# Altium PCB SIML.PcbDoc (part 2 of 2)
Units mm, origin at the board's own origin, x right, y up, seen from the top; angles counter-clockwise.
Board outline 80.5 x 51.25 mm, 2 copper layers (Top Layer, Top, Bottom Layer, Bottom), stack 1.571 mm thick; 94 components, 58 nets, 279 pads, 160 vias.
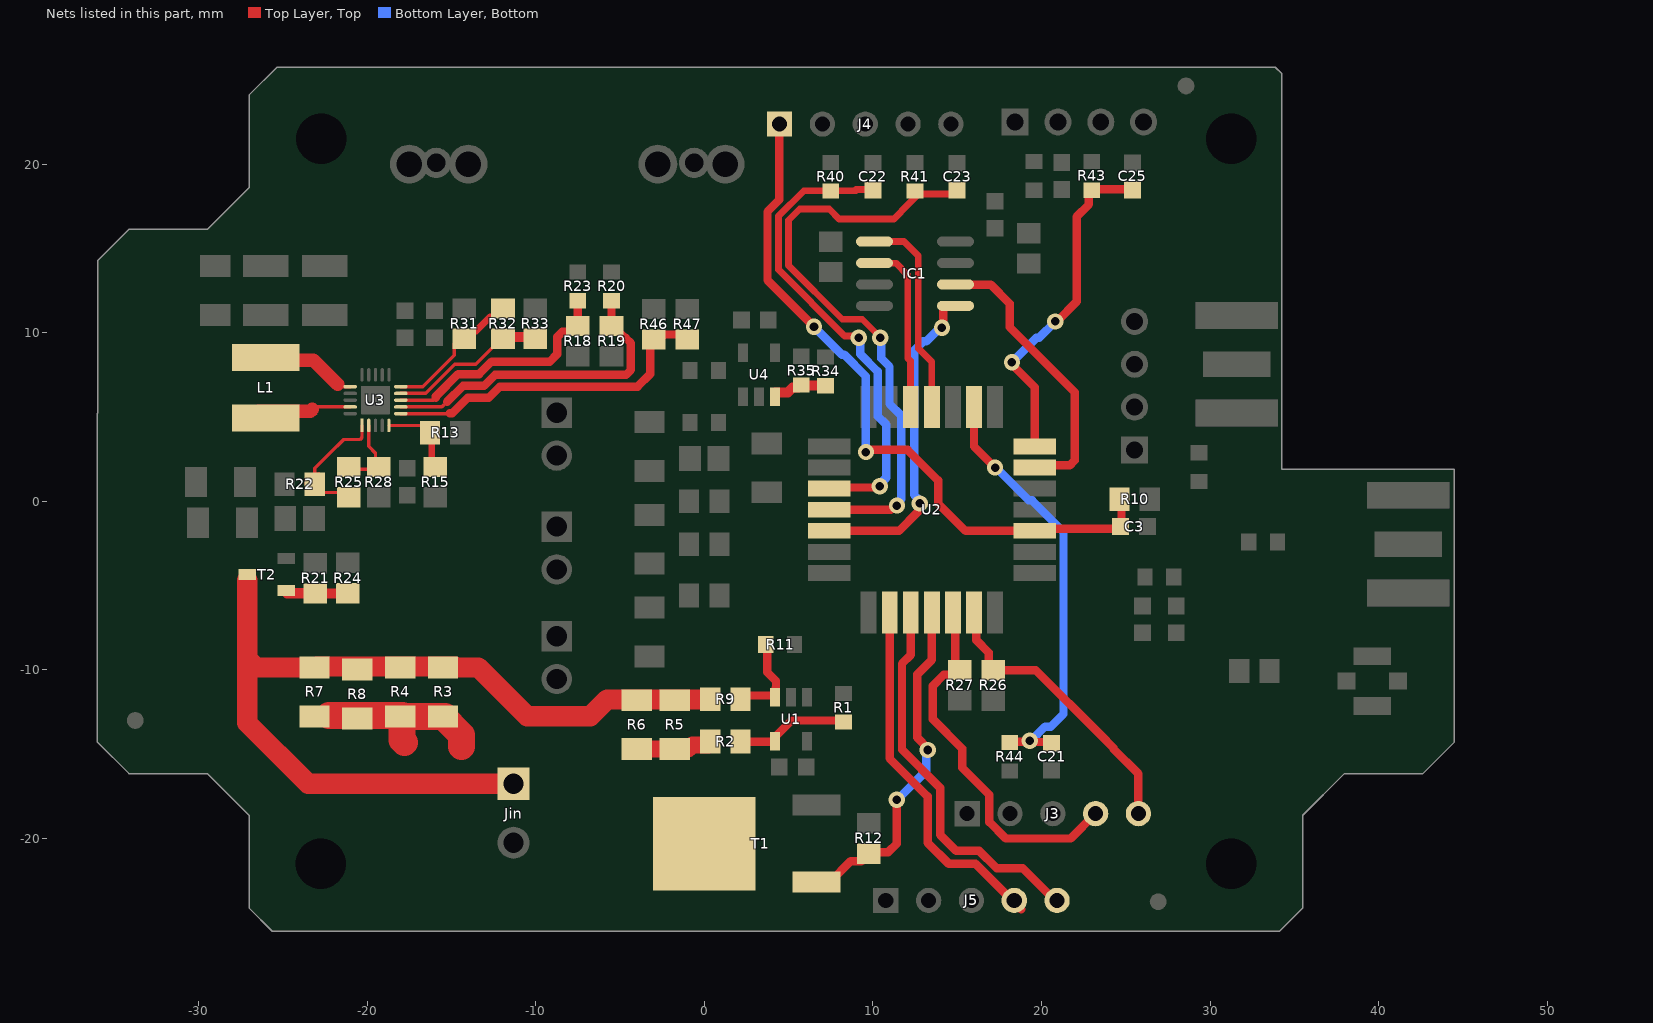
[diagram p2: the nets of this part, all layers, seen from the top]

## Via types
v1: diameter 0.965, hole 0.508, Top Layer, Top to Bottom Layer, Bottom, tented both sides, 146 vias
v2: diameter 0.8, hole 0.4, Top Layer, Top to Bottom Layer, Bottom, tented both sides, 10 vias
v3: diameter 0.965, hole 0.508, Top Layer, Top to Bottom Layer, Bottom, 4 vias

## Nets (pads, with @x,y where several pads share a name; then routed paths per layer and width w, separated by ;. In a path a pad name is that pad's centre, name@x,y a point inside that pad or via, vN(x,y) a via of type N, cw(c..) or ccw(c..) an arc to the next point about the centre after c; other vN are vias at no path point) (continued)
NetJin_1: Jin.1 R3.1 R4.1 R5.1 R6.1 R7.1 R8.1 R9.1 T2.3 | length 55.1
  Top Layer, Top w1.2: T2.3@-27.1,-4.673 -27.1,-9.349 ; R7.1@-23.114,-9.853 -26.596,-9.853 -27.1,-9.349 ; R7.1@-22.987,-9.8 -18.034,-9.8 -14.75,-9.8 -14.7,-9.85 -13.4,-9.85 -10.5,-12.75 -6.75,-12.75 -5.75,-11.75 -4,-11.75 R9.1@0.35,-11.75 ; Jin.1@-11.592,-17.033 Jin.1@-11.58,-17.045 ; Jin.1@-11.455,-16.92 Jin.1@-11.455,-16.753 ; Jin.1@-11.311,-16.753 Jin.1@-11.455,-16.753 ; -27.1,-9.349 -27.1,-13.15 -23.497,-16.753 Jin.1@-11.455,-16.753
NetL1_1: L1.1 U3.19 | length 6
  Top Layer, Top w0.2: -23.241,5.448 -23.088,5.6 U3.19@-21,5.6
  Top Layer, Top w0.8: L1.1@-26.8,5 -26.467,5.333 -23.356,5.333 -23.241,5.448
NetL1_2: L1.2 U3.16 | length 5.5
  Top Layer, Top w0.2: -21.749,6.941 -21.608,6.8 U3.16@-21,6.8
  Top Layer, Top w0.8: L1.2@-25.868,8.379 -23.187,8.379 -21.749,6.941
NetR1_1: R1.1 R2.2 U1.4 | length 6.8
  Top Layer, Top w0.5: R2.2@1.9,-14.25 U1.4@4.172,-14.25 ; U1.4@4.184,-13.987 4.251,-13.921 4.263,-13.921 5.184,-13 8.15,-13 R1.1@8.25,-13.1
NetR2_1: R2.1 R3.2 R4.2 R5.2 R6.2 R7.2 R8.2 T1.3 | length 15.4
  Top Layer, Top w1: R6.2@-4,-14.7 R5.2@-1.75,-14.7 -0.95,-14.7 -0.7,-14.45 0.25,-14.45 0.35,-14.35 R2.1@0.35,-14.25
  Top Layer, Top w1.6: R7.2@-22.25,-12.7 -20.447,-12.7 -19.75,-12.7 R4.2@-17.907,-12.7 ; R4.2@-18.034,-12.753 -17.934,-12.853 -17.934,-14.153 -17.784,-14.303 ; R4.2@-17.907,-12.753 R3.2@-15.367,-12.753 ; R3.2@-15.494,-12.753 -14.393,-13.854 -14.393,-14.549
NetR9_2: R9.2 R11.2 U1.3 | length 5.6
  Top Layer, Top w0.5: R9.2@1.908,-11.519 4.201,-11.519 4.251,-11.469 4.251,-11.075 4.256,-11.07 4.256,-10.656 3.749,-10.149 3.749,-8.599 R11.2@3.65,-8.5
NetR13_1: R13.1 R15.2 U3.5 | length 6.1
  Top Layer, Top w0.2: U3.5@-18.7,4.5 -16.703,4.5 -16.072,3.869 -16.072,2.113 R15.2@-16.002,2.043 ; R15.2@-16.256,2.143 R13.1@-16.256,3.451
NetR18_1: R18.1 R23.1 U3.8 | length 14.5
  Top Layer, Top w0.2: U3.8@-18,6 -16.065,6 -15.915,6.15
  Top Layer, Top w0.5: -15.915,6.15 -15.915,6.23 -14.598,7.548 -13.354,7.548 -12.615,8.287 -9.157,8.287 -8.717,8.727 -8.717,9.757 -8.424,10.05 -7.85,10.05 R18.1@-7.5,10.4 R23.1@-7.5,11.9
NetR19_1: R19.1 R20.1 U3.7 | length 19.2
  Top Layer, Top w0.2: U3.7@-18,5.6 -15.555,5.6 -15.241,5.914
  Top Layer, Top w0.5: -15.241,5.914 -14.308,6.848 -13.064,6.848 -12.411,7.5 -4.643,7.5 -4.35,7.793 -4.35,9.386 -4.66,9.696 -4.696,9.696 -5.4,10.4 R19.1@-5.5,10.4 R20.1@-5.5,11.9
NetR21_1: R21.1 R24.2 T2.1 | length 3.6
  Top Layer, Top w0.6: T2.1@-24.748,-5.466 -24.558,-5.466 -24.548,-5.456 R21.1@-23.106,-5.456 ; R21.1@-23.075,-5.475 -23.063,-5.462 -21.162,-5.462 R24.2@-21.15,-5.45
NetR22_1: R22.1 R25.2 U3.1 | length 9.8
  Top Layer, Top w0.2: R22.1@-23.603,1.016 -23.603,1.109 -23.103,1.609 R22.1@-22.872,1.609 ; R22.1@-23.104,1.017 -23.104,1.953 ; R22.1@-23.104,1.609 -23.104,1.953 ; R22.1@-22.853,1.628 -22.672,1.447 R22.1@-23.103,1.016 -22.611,0.524 -21.49,0.524 R25.2@-21.082,0.116 ; U3.1@-20.3,4.5 -20.3,3.784 -20.417,3.667 -21.386,3.667 -22.237,2.816 -22.241,2.816 -23.104,1.953
NetR25_1: R25.1 R28.2 U3.2 | length 4.8
  Top Layer, Top w0.2: R25.1@-21.5,1.9 -19.5,1.9 -19.5,2.863 -19.9,3.263 U3.2@-19.9,4.5
NetR31_1: R31.1 R32.2 U3.10 | length 8.1
  Top Layer, Top w0.2: U3.10@-18,6.8 -16.975,6.8 -16.689,6.8 -14.824,8.665 -14.824,9.339 R31.1@-14.5,9.663
  Top Layer, Top w0.3: R31.1@-14.224,9.641 -13.99,9.641 -13.99,9.775 -13.674,10.091 R31.1@-13.54,10.091 ; -12.681,10.95 -12.664,10.95 -12.623,10.991 -12.409,10.991 R32.2@-12,11.4
  Top Layer, Top w0.4: R31.1@-13.54,10.091 -12.681,10.95
NetR32_1: R32.1 R33.2 U3.9 | length 9.2
  Top Layer, Top w0.2: U3.9@-18,6.4 -16.523,6.4 -14.795,8.128 -13.551,8.128 -12.25,9.429 R32.1@-12.25,9.5
  Top Layer, Top w0.6: R32.1@-12.25,9.6 -12.1,9.75 -10.4,9.75 R33.2@-10.25,9.6
NetR34_1: R34.1 R35.2 U4.3 | length 3.5
  Top Layer, Top w0.6: U4.3@4.2,6.2 4.2,6.45 4.95,6.45 5.25,6.75 5.6,6.75 R35.2@5.75,6.9 5.775,6.875 7.175,6.875 R34.1@7.2,6.85
NetR46_1: R46.1 R47.2 U3.6 | length 19.8
  Top Layer, Top w0.2: U3.6@-18,5.2 -16.348,5.2 -16.347,5.199 -15.101,5.199
  Top Layer, Top w0.5: -15.101,5.214 -14.951,5.214 -14.018,6.148 -12.774,6.148 -12.121,6.8 -3.95,6.8 -3.2,7.55 -3.2,9.25 -2.701,9.749 R46.1@-2.501,9.749 ; R46.1@-2.501,9.895 -1.976,9.895 R47.2@-1.048,9.895
PWR_WKP: C21.1 R44.1 U2.23 | length 25.8
  Top Layer, Top w0.5: U2.23@16,5.596 16,3.25 v1(17.25,2) ; R44.1@18.125,-14.3 18.175,-14.25 19.262,-14.25 v1(19.311,-14.201) 19.386,-14.275 20.525,-14.275 C21.1@20.6,-14.35
  Bottom Layer, Bottom w0.5: v1(17.25,2) 17.306,2 19.256,0.05 19.45,0.05 21.311,-1.811 21.311,-12.614 20.562,-13.363 20.217,-13.363 19.379,-14.201 v1(19.311,-14.201)
RESET: C3.2 J4.1 R10.1 U2.17 | length 42.2
  Top Layer, Top w0.5: J4.1@4.47,22.375 4.445,22.35 4.445,17.882 3.75,17.187 3.75,13.111 v1(6.509,10.352) ; v1@9.906,3.048 12.065,3.048 13.87,1.243 13.87,-0.12 15.5,-1.75 U2.17@19.596,-1.75 19.721,-1.625 24.75,-1.625 24.75,0.331 R10.1@24.557,0.524
  Bottom Layer, Bottom w0.5: v1(6.509,10.352) 8.17,8.691 8.309,8.691 9.588,7.412 v1(9.588,2.921)
SCL: J3.5 R26.1 U2.13 | length 17.4
  Top Layer, Top w0.5: U2.13@16,-6.596 16.14,-6.736 16.14,-8.244 16.863,-8.968 16.863,-9.738 R26.1@17.15,-10.025 19.672,-10.025 23.52,-13.872 24.25,-14.603 24.25,-14.653 25.755,-16.158 J3.5@25.755,-18.525
SDA: J3.4 R27.1 U2.12 | length 22.1
  Top Layer, Top w0.5: U2.12@14.75,-6.596 14.888,-6.733 14.888,-9.813 15.025,-9.95 14.675,-10.3 14.197,-10.3 13.558,-10.939 13.558,-12.926 15.295,-14.663 15.295,-15.795 16.915,-17.415 16.915,-19.03 17.885,-20 21.74,-20 J3.4@23.215,-18.525
"SPI2 CS": IC1.1 U2.25 | length 12.2
  Top Layer, Top w0.4: IC1.1@10.1,15.405 11.845,15.405 12.7,14.55 12.7,9.068 13.5,8.268 U2.25@13.5,5.596
"SPI2 MISO": IC1.2 U2.26 | length 10.2
  Top Layer, Top w0.4: IC1.2@10.1,14.135 10.11,14.125 11.375,14.125 12.065,13.435 12.065,8.505 12.237,8.333 U2.26@12.237,5.609
"SPI2 MOSI": IC1.5 U2.5 | length 19.7
  Top Layer, Top w0.5: U2.5@7.404,-1.75 11.551,-1.75 12.694,-0.606 12.694,-0.216 v1(12.783,-0.127) ; v1(14.097,10.287) 14.186,10.376 14.186,11.549 14.232,11.595 IC1.5@14.9,11.595
  Bottom Layer, Bottom w0.5: v1(12.783,-0.127) 12.694,-0.038 12.694,0.133 12.446,0.381 12.446,8.946 12.991,9.491 13.175,9.491 13.971,10.287 v1(14.097,10.287)
"SPI2 SCK": IC1.6 U2.20 | length 17.1
  Top Layer, Top w0.5: IC1.6@14.9,12.865 14.919,12.846 16.999,12.846 18.11,11.735 18.11,10.338 21.971,6.477 21.971,2.42 21.678,2.127 19.723,2.127 U2.20@19.596,2
STRT_MEAS: R12.2 T1.1 U2.11 | length 20.8
  Top Layer, Top w0.5: T1.1@6.65,-22.58 7.45,-22.58 8.68,-21.35 9.325,-21.35 R12.2@9.757,-20.918 ; R12.2@9.832,-20.818 10.907,-20.818 11.425,-20.3 v3(11.425,-17.7) ; v3(13.25,-14.75) 13.25,-14.624 12.637,-14.011 12.637,-10.263 13.5,-9.4 U2.11@13.5,-6.596
  Bottom Layer, Bottom w0.5: v3@11.35,-17.8 13.167,-15.983 13.167,-14.833 v3(13.25,-14.75)
SWCLK: C23.1 R41.1 U2.4 | length 35.8
  Top Layer, Top w0.4: v1(10.441,9.703) 10.441,9.73 9.373,10.798 8.188,10.798 5,13.986 5,16.669 5.665,17.335 7.415,17.335 8,16.75 11.25,16.75 12.125,17.625 12.725,18.225 14.775,18.225 C23.1@15,18.45
  Top Layer, Top w0.5: U2.4@7.404,-0.5 11.058,-0.5 11.304,-0.254 v1(11.43,-0.254)
  Bottom Layer, Bottom w0.5: v1(10.441,9.703) 10.51,9.634 10.51,8.47 10.988,7.992 10.988,5.776 11.684,5.08 11.684,0.126 11.43,-0.128 v1(11.43,-0.254)
SWDIO: C22.1 R40.1 U2.3 | length 28.6
  Top Layer, Top w0.4: 9,18.45 8.968,18.418 7.5,18.418 5.9,18.418 4.4,16.918 4.4,13.738 8.327,9.811 9.056,9.811 v1(9.164,9.703) ; 9,18.5 C22.1@10,18.5
  Top Layer, Top w0.5: U2.3@7.404,0.75 7.474,0.82 10.345,0.82 v1(10.414,0.889)
  Bottom Layer, Bottom w0.5: v1(9.164,9.703) 9.253,9.614 9.253,8.736 10.288,7.702 10.288,5.057 10.795,4.55 10.795,1.396 10.414,1.015 v1(10.414,0.889)
TIM1CH2: C25.1 R43.1 U2.21 | length 19.9
  Top Layer, Top w0.5: v1(18.25,8.25) 18.25,8.124 19.596,6.778 U2.21@19.596,3.25 ; v1(20.828,10.668) 20.914,10.668 22.098,11.852 22.098,16.891 22.819,17.612 22.819,18.286 R43.1@22.987,18.454 ; R43.1@23.33,18.504 C25.1@25.4,18.504
  Bottom Layer, Bottom w0.5: v1(18.25,8.25) 19.7,9.7 19.86,9.7 v1(20.828,10.668)
U1_RX: J5.4 U2.9 | length 21.8
  Top Layer, Top w0.5: U2.9@11,-6.596 11,-15.25 13.25,-17.5 13.25,-20.25 14.5,-21.5 16.09,-21.5 18.327,-23.737 J5.4@18.798,-24.208
U1_TX: J5.5 U2.10 | length 22.8
  Top Layer, Top w0.5: U2.10@12.25,-6.596 12.25,-9.106 11.731,-9.625 11.731,-14.731 14,-17 14,-19.785 14.94,-20.725 16.305,-20.725 17.339,-21.759 18.889,-21.759 J5.5@20.845,-23.715
pads on no net: J5.1 U2.28 U3.17

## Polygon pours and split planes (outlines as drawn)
GND on Bottom Layer, Bottom "NONET_L-01_P-001" (solid, remove dead copper, pour order 4): 34.544,1.524 33.5,2.568 33.5,24.5 -6085.235,24.5 -24.25,25.75 -26.25,23.75 -26.25,18.5 -29,15.75 -31.75,15.75 -32,15.5 -32,-15.5 -29.5,-15.5 -20,-25 30.785,-25 30.785,-14 44,-14 44,1.524
3.3V on Bottom Layer, Bottom "NONET_L-01_P-001" (solid, pour order 0): -18.285,11.239 -18.285,8.489 -17.285,7.489 -15.785,7.489 -15.785,10.739 -16.285,11.239
GND on Top Layer, Top "NONET_L-01_P-001" (solid, remove dead copper, pour order 2): 34.544,1.524 33.5,2.568 33.5,24.5 -6085.235,24.5 -24.25,25.75 -26.25,23.75 -26.25,18.5 -29,15.75 -31.75,15.75 -32,15.5 -32,-15.5 -29.5,-15.5 -20,-25 30.785,-25 30.785,-14 44,-14 44,1.524
NetR2_1 on Top Layer, Top "NONET_L-01_P-001" (solid, remove dead copper, pour order 1): -23.75,-14.75 -23,-15.5 -8.75,-15.5 -8.75,-25 2.5,-25 3.25,-24.25 3.25,-17.5 2.75,-17.5 1,-15.75 1,-13 -15,-13 -23.75,-13

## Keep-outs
Top Layer, Top:
  circle w0.254: c-33.75,-13 r1
  circle w0.254: c26.924,-23.749 r1
Keep-Out Layer, Board:
  circle w0.254: c-22.749,-21.475 r3.5
  circle w0.254: c31.258,21.485 r3
  circle w0.254: c31.242,-21.45 r3.5
  circle w0.254: c-22.725,21.5 r3.5
  lines w0.2: -37.168,-13.786 ccw(c-34.17,-13.786) -34.17,-16.785 -33.417,-16.785 cw(c-33.414,-22.68) -27.519,-22.682 -27.519,-23.435 ccw(c-24.52,-23.436) -24.52,-26.434 33.052,-26.434 ccw(c33.053,-23.436) 36.051,-23.435 36.051,-22.682 cw(c41.948,-22.682) 41.949,-16.785 42.702,-16.785 ccw(c42.702,-13.786) 45.701,-13.786 45.701,13.788 ccw(c42.702,13.788) 42.702,16.787 41.949,16.787 cw(c41.948,22.684) 36.051,22.684 36.051,23.437 ccw(c33.053,23.438) 33.052,26.436 -24.52,26.436 ccw(c-24.52,23.438) -27.519,23.437 -27.519,22.684 cw(c-33.416,22.684) -33.417,16.787 -34.17,16.787 ccw(c-34.17,13.788) -37.168,13.788 -37.168,-13.786

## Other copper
Top Layer, Top:
  rectangle net 3.3V: 14.75,-12.25 17.5,-11.25
  region net 3.3V: -19.178,7.854 -19.1,7.854 -18.416,8.538 -18.289,8.538 -18.289,8.665 -18.67,9.046 -19.178,8.538
  region net NetC13_2: -20.3,7.5 -21,7.5 -22.25,8.75 -22.25,10.5 -21.25,10.5 -21.25,9.25 -20.3,8.3 -20.3,8.193
  pour cut-out: -7.75,-27.75 -7.75,-25.75 -8.5,-25.75 -8.5,-27.75
  pour cut-out: 3.302,-25.4 3.302,-16.9 5.072,-16.9 5.072,-25.4
  region net 3.3V: -16.891,10.033 -16.891,7.969 -18.064,7.969 -18.064,7.979 -18.772,8.688 -18.667,8.793 -18.667,9.77 -18.226,10.211 -17.125,10.211
  pour cut-out: 46.964,-8.524 47.472,-9.032 49.25,-9.032 49.25,-4.968 49.123,-4.841 46.837,-4.841
  pour cut-out: 38.608,-4.572 44.069,-4.572 44.069,-0.381 43.688,0 38.608,0
  pour cut-out: -28.596,10 -29.358,9.238 -29.358,4.608 -27.892,3.142 -24.278,3.142 -23.135,4.285 -23.135,8.73 -24.405,10
  pour cut-out: -17.78,-10.922 -17.78,-12.954 4.318,-12.954 4.445,-12.827 4.445,-10.922 -19.685,-10.922
  pour cut-out: -10.986,6.314 -10.986,1.524 -6.032,1.524 -6.032,6.35 -10.975,6.35
  pour cut-out: -11.245,-0.036 -11.245,-4.826 -6.292,-4.826 -6.292,0 -11.234,0
  text "SIML V1.0" at 26.924,-17.78 h4

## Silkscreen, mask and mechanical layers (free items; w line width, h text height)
Top Overlay, Top Silk:
  circle w0.305: c-22.749,-21.475 r2.3
  circle w0.305: c31.258,21.485 r2.3
  circle w0.305: c31.242,-21.45 r2.3
  circle w0.305: c-22.725,21.5 r2.3
  text "SIML V1.0" at 26.924,-17.78 h4
Mechanical 1:
  drawing of 435 lines, arcs and shapes, not listed
  text "8" at -461.852,-417.532 h2.65
  text "2" at -763.173,-417.646 h2.65
  text "7" at -512.587,-417.625 h2.65
  text "1" at -808.185,-417.675 h2.65
  text "3" at -712.432,-417.676 h2.65
  text "10cm-Scale with caution as distortion can occur" at -585.235,-418.569 h1.5
  text "A" at -435.643,-443.486 h2.65
  text "A" at -829.42,-444.285 h2.65
  text "B" at -435.636,-501.391 h2.65
  text "B" at -829.677,-502.133 h2.65
  text "C" at -829.848,-556.499 h2.65
  text "C" at -435.569,-556.527 h2.65
  text "D" at -435.734,-610.942 h2.65
  text "D" at -829.81,-612.674 h2.65
  text "Indrivetec AG  confidential" at -525.933,-643.772 h3.5
  text "general tolerances (SN EN 22768-1/-2): ISO 2768-mK" at -616.018,-644.984 h1.8
  text "This document contains intellectual property belonging to Indrivetec AG. Any reproduction," at -615.346,-649.362 h1.5
  text "replacement for:" at -458.38,-650.103 h1.8
  text "checked :" at -525.933,-650.272 h1.8
  text "distribution or exhibition is not allowed without the written consent of Indrivetec AG." at -615.346,-651.862 h1.5
  text "Unauthorized use, disclosure, dissemination or duplication of any of the information contained" at -615.346,-654.362 h1.5
  text "checked eng:" at -526.064,-655.734 h1.8
  text "herein may result in liability under applicable laws." at -615.346,-656.862 h1.5
  text "INDRIVETEC" at -614.935,-660.372 h4.76
  text "Indrivetec AG" at -551.637,-660.977 h2
  text "checked  prod:" at -526.044,-661.241 h1.8
  text "scale:" at -458.38,-661.285 h1.8
  text "Hagenholzstrasse 71, CH-8050 Zürich" at -551.96,-663.977 h2
  text "drawn by:" at -526.012,-666.648 h1.8
  text "www.indrivetec.ch" at -551.853,-666.977 h2
  text "Innovative Drive Technologies AG" at -614.899,-667.578 h1.55
  text "E" at -435.485,-668.594 h2.65
  text "E" at -435.485,-668.594 h2.65
  text "E" at -435.166,-668.594 h2.65
  text "E" at -829.715,-669.708 h2.65
  text "description:" at -526,-671.224 h1.8
  text "material:" at -458.374,-672.387 h1.8
  text "Subject to rectifying modification and amendments" at -614.902,-672.67 h1.8
  text "article number:" at -517.062,-684.372 h1.8
  text "CAD-name:" at -509.742,-687.552 h1.8
  text "format:" at -458.612,-689.06 h1.8
  text "/" at -442.249,-693.956 h2.38
  text "page / of:" at -458.612,-694.516 h1.8
  text "6" at -563.395,-698.541 h2.65
  text "5" at -615.388,-698.553 h2.65
  text "4" at -661.49,-698.57 h2.65
  text "7" at -513.661,-698.625 h2.65
  text "8" at -459.972,-698.664 h2.65
  text "3" at -713.194,-698.68 h2.65
  text "1" at -808.463,-698.727 h2.65
  text "2" at -763.955,-698.727 h2.65
Mechanical 2:
  drawing of 629 lines, arcs and shapes, not listed
  text "8" at -461.852,-417.532 h2.65
  text "2" at -763.173,-417.646 h2.65
  text "7" at -512.587,-417.625 h2.65
  text "1" at -808.185,-417.675 h2.65
  text "3" at -712.432,-417.676 h2.65
  text "10cm-Scale with caution as distortion can occur" at -585.235,-418.569 h1.5
  text "A" at -435.643,-443.486 h2.65
  text "A" at -829.42,-444.285 h2.65
  text "A" at -785.235,-485.136 h5
  text "A" at -629.97,-485.136 h5
  text "B" at -435.636,-501.391 h2.65
  text "B" at -829.677,-502.133 h2.65
  text "SECTION A-A" at -706.701,-534.297 h5
  text "C" at -829.848,-556.499 h2.65
  text "C" at -435.569,-556.527 h2.65
  text "D" at -435.734,-610.942 h2.65
  text "D" at -829.81,-612.674 h2.65
  text "Indrivetec AG  confidential" at -525.933,-643.772 h3.5
  text "general tolerances (SN EN 22768-1/-2): ISO 2768-mK" at -616.018,-644.984 h1.8
  text "This document contains intellectual property belonging to Indrivetec AG. Any reproduction," at -615.346,-649.362 h1.5
  text "replacement for:" at -458.38,-650.103 h1.8
  text "checked :" at -525.933,-650.272 h1.8
  text "distribution or exhibition is not allowed without the written consent of Indrivetec AG." at -615.346,-651.862 h1.5
  text "Unauthorized use, disclosure, dissemination or duplication of any of the information contained" at -615.346,-654.362 h1.5
  text "checked eng:" at -526.064,-655.734 h1.8
  text "herein may result in liability under applicable laws." at -615.346,-656.862 h1.5
  text "INDRIVETEC" at -614.935,-660.372 h4.76
  text "Indrivetec AG" at -551.637,-660.977 h2
  text "checked  prod:" at -526.044,-661.241 h1.8
  text "scale:" at -458.38,-661.285 h1.8
  text "Hagenholzstrasse 71, CH-8050 Zürich" at -551.96,-663.977 h2
  text "drawn by:" at -526.012,-666.648 h1.8
  text "www.indrivetec.ch" at -551.853,-666.977 h2
  text "Innovative Drive Technologies AG" at -614.899,-667.578 h1.55
  text "E" at -435.485,-668.594 h2.65
  text "E" at -435.485,-668.594 h2.65
  text "E" at -435.166,-668.594 h2.65
  text "E" at -829.715,-669.708 h2.65
  text "description:" at -526,-671.224 h1.8
  text "material:" at -458.374,-672.387 h1.8
  text "Subject to rectifying modification and amendments" at -614.902,-672.67 h1.8
  text "article number:" at -517.062,-684.372 h1.8
  text "CAD-name:" at -509.742,-687.552 h1.8
  text "format:" at -458.612,-689.06 h1.8
  text "/" at -442.249,-693.956 h2.38
  text "page / of:" at -458.612,-694.516 h1.8
  text "6" at -563.395,-698.541 h2.65
  text "5" at -615.388,-698.553 h2.65
  text "4" at -661.49,-698.57 h2.65
  text "7" at -513.661,-698.625 h2.65
  text "8" at -459.972,-698.664 h2.65
  text "3" at -713.194,-698.68 h2.65
  text "1" at -808.463,-698.727 h2.65
  text "2" at -763.955,-698.727 h2.65
BOARD:
  lines w0.3: -36,5.225 -36,-14.275 -34.125,-16.15 -29.475,-16.15 -27,-18.625 -27,-24.125 -25.625,-25.5 34.125,-25.5 35.5,-24.125 35.5,-18.625 37.975,-16.15 42.625,-16.15 44.5,-14.275 44.5,-5.225 44.5,1.905 34.25,1.905 34.25,25.375 33.875,25.75 -25.35,25.75 -26.975,24.125 -26.975,18.625 -29.45,16.15 -34.1,16.15 -35.975,14.275 -35.975,5.225
TOP ASSY:
  text "'.VariantName'" at -33.35,43.725 h3
ZP90.60.40.U:
  drawing of 642 lines, arcs and shapes, not listed
Mechanical 10:
  circle w0.2: c-99.429,-182.665 r2.25
  circle w0.2: c-99.429,-182.665 r1
  lines w0.2: -112.292,-141.115 -107.292,-141.115 ; -112.292,-85.715 -107.292,-85.715 ; -112.292,-30.315 -107.292,-30.315 ; -112.292,25.067 -107.292,25.067 ; -111.292,-141.115 -107.292,-141.115 ; -107.292,-190.975 -84.792,-190.975 ; -107.292,-179.895 -84.792,-179.895 ; -107.292,-174.355 -84.792,-174.355 ; -107.292,-168.815 72.708,-168.815 ; -107.292,-163.275 -17.292,-163.275 ; -107.292,-157.735 72.708,-157.735 ; -107.292,-152.195 -17.292,-152.195 ; -107.292,-146.655 72.708,-146.655 ; -103.25,-182.665 -87.057,-182.665 ; -100.504,-185.435 -107.292,-185.435 72.708,-185.435 ; -99.429,-185.191 -99.429,-180.032 ; -96.042,-196.515 -96.042,-190.975 -96.042,-185.435 ; -84.792,-146.655 -84.792,-196.515 ; -62.292,-168.815 -62.292,-146.655 ; -60.064,-200.515 -60.064,-196.515 ; -60.064,81.719 -60.064,85.719 ; -39.792,-168.815 -39.792,-146.655 ; -17.292,-190.975 72.708,-190.975 ; -17.292,-179.895 72.708,-179.895 ; -17.292,-174.355 72.708,-174.355 ; -17.292,-141.115 -17.292,-196.515 ; -10.064,-200.515 -10.064,-196.515 ; -10.064,81.719 -10.064,85.719 ; 2.708,-196.515 2.708,-174.355 ; 39.936,-200.515 39.936,-196.515 ; 39.936,81.719 39.936,85.719 ; 67.708,-196.515 67.708,-174.355 ; 72.708,-135.715 76.708,-135.715 ; 72.708,-125.715 74.708,-125.715 ; 72.708,-115.715 74.708,-115.715 ; 72.708,-105.715 74.708,-105.715 ; 72.708,-95.715 74.708,-95.715 ; 72.708,-75.715 74.708,-75.715 ; 72.708,-65.715 74.708,-65.715 ; 72.708,-55.715 74.708,-55.715 ; 72.708,-45.715 74.708,-45.715 ; 72.708,-35.715 76.708,-35.715 ; 72.708,25.085 76.708,25.085 ; 74.708,-135.715 74.708,-35.715 ; 76.708,-141.115 72.708,-141.115 ; 77.621,-57.781 86.938,-57.781 ; -117.292,-200.708 -117.292,-206.281 -111.718,-206.281 ; -117.292,-200.708 -111.718,-206.281 ; -117.292,-200.708 -117.292,85.413 ; -117.292,85.413 -111.986,90.719 ; -117.292,85.413 -117.292,90.719 -111.986,90.719 ; -111.986,90.719 86.938,90.719 ; -111.718,-206.281 86.674,-206.281 ; -107.292,-196.515 -107.292,81.719 72.708,81.719 72.708,-196.515 ; -107.292,-196.515 72.708,-196.515 ; -107.292,-196.515 -84.792,-196.515 ; -107.292,-196.515 72.708,-196.515 ; -107.292,-141.115 72.708,-141.115 ; -84.792,-196.515 -17.292,-196.515 ; -84.792,-196.515 -17.292,-196.515 ; 72.708,-196.515 72.708,-141.115 ; 86.674,-206.281 92.708,-206.281 92.708,-200.216 ; 86.674,-206.281 92.708,-200.216 ; 86.938,90.719 92.708,84.949 ; 86.938,90.719 92.708,90.719 92.708,84.949 ; 92.708,-200.216 92.708,84.949 ; -112.292,-200.515 76.708,-200.515 76.708,85.719 -112.292,85.719 -112.292,-200.515 ; -94.145,-184.915 -88.145,-183.665 -88.145,-181.665 -94.145,-180.415 -94.145,-184.915 ; 72.708,-85.715 76.708,-85.715 72.708,-85.715
  text "1" at 60.653,82.263 h5
  text "4" at -81.714,82.136 h5
  text "2" at 19.759,82.136 h5
  text "3" at -31.676,82.009 h5
  text "A" at -108.003,56.99 h5
  text "A" at 76.02,55.593 h5
  text "B" at -108.257,-0.922 h5
  text "10cm-Scale with caution as distortion can occur" at 73.861,-33.053 h2.3 r270
  text "C" at -108.257,-55.913 h5
  text "D" at -108.294,-110.434 h5
  text "general tolerances (SN EN 22768-1/-2): ISO 2768-mK" at 71.973,-144.858 h3.2
  text "Indrivetec AG  confidential" at -17.73,-146.186 h6
  text "Copying of this document and giving it to others and the use or communication of the contents" at 71.95,-149.299 h2.3
  text "replacement for:" at -85.41,-150.104 h3.2
  text "checked :" at -17.857,-150.273 h3.2
  text "thereof, are forbidden without express authority. Offenders are liable to the payment of damages." at 71.95,-151.799 h2.3
  text "All rights are reserved in the event of the a patent or the registration of a utility or design." at 71.95,-154.299 h2.3
  text "checked eng:" at -17.726,-155.735 h3.2
  text "Indrivetec AG" at 71.95,-156.799 h2.3
  text "Indrivetec AG" at 21.918,-161.069 h3.4
  text "checked  prod:" at -17.747,-161.242 h3.2
  text "scale:" at -85.41,-161.285 h3.2
  text "INDRIVETEC" at 71.575,-163.99 h6.5
  text "Hagenholzstrasse 71, CH-8050 Zürich" at 35.38,-164.244 h3.4
  text "drawn by:" at -17.778,-166.649 h3.2
  text "www.indrivetec.ch" at 24.585,-167.165 h3.4
  text "1:1" at -87.491,-167.469 h4.2
  text "Innovative Drive Technologies AG" at 71.702,-167.927 h2.6
  text "E" at -107.876,-168.054 h5
  text "E" at 75.893,-169.705 h5
  text "LK" at -45.53,-169.903 h5
  text "description:" at -17.79,-171.224 h3.2
  text "material:" at -85.417,-172.387 h3.2
  text "Subject to rectifying modification and amendments" at 71.111,-172.671 h3.2
  text "d" at 71.029,-177.991 h3.2
  text "EP-17-00**-AA-I-E-A" at -23.218,-178.07 h5
  text "c" at 70.95,-183.485 h3.2
  text "article number:" at -18.818,-184.07 h3.2
  text "000-0000-00" at -30.421,-184.613 h5
  text "b" at 70.969,-188.959 h3.2
  text "format:" at -85.179,-189.061 h3.2
  text "A4" at -100.636,-189.732 h4.2
  text "CAD-name:" at -23.318,-191.32 h3.2
  text "LSB / LSB - P  V5.1" at -36.64,-194.414 h5
  text "modification:" at 66.769,-194.507 h3.2
  text "page / of:" at -85.179,-194.517 h2.9
  text "name, date:" at 1.875,-194.521 h3.2
  text "1" at -99.367,-195.187 h4.2
  text "1" at -104.366,-195.229 h4.2
  text "/" at -102.303,-195.227 h4.2
  text "3" at -32.184,-199.931 h5
  text "2" at 17.6,-199.931 h5
  text "4" at -85.143,-200.058 h5
  text "1" at 60.145,-200.058 h5
Mechanical 11:
  circle w0.2: c74.631,-182.438 r2.25
  circle w0.2: c74.631,-182.438 r1
  lines w0.2: -111.737,-57.555 -102.42,-57.555 ; -101.506,-140.888 -97.506,-140.888 ; -101.506,-135.488 -97.506,-135.488 ; -101.506,-35.488 -97.506,-35.488 ; -101.506,25.312 -97.506,25.312 ; -99.506,-135.488 -99.506,-35.488 ; -99.506,-125.488 -97.506,-125.488 ; -99.506,-115.488 -97.506,-115.488 ; -99.506,-105.488 -97.506,-105.488 ; -99.506,-95.488 -97.506,-95.488 ; -99.506,-75.488 -97.506,-75.488 ; -99.506,-65.488 -97.506,-65.488 ; -99.506,-55.488 -97.506,-55.488 ; -99.506,-45.488 -97.506,-45.488 ; -97.507,-190.748 -7.507,-190.748 ; -97.507,-185.208 82.493,-185.208 75.705,-185.208 ; -97.507,-179.668 -7.507,-179.668 ; -97.507,-174.128 -7.507,-174.128 ; -97.507,-168.588 82.493,-168.588 ; -97.507,-157.508 82.493,-157.508 ; -97.507,-146.428 82.493,-146.428 ; -92.507,-196.288 -92.507,-174.128 ; -64.735,-200.288 -64.735,-196.288 ; -64.735,81.945 -64.735,85.945 ; -27.507,-196.288 -27.507,-174.128 ; -14.735,-200.288 -14.735,-196.288 ; -14.735,81.945 -14.735,85.945 ; -7.507,-163.048 82.493,-163.048 ; -7.507,-151.968 82.493,-151.968 ; -7.507,-140.888 -7.507,-196.288 ; 14.993,-168.588 14.993,-146.428 ; 35.265,-200.288 35.265,-196.288 ; 35.265,81.945 35.265,85.945 ; 37.493,-168.588 37.493,-146.428 ; 59.993,-190.748 82.493,-190.748 ; 59.993,-179.668 82.493,-179.668 ; 59.993,-174.128 82.493,-174.128 ; 59.993,-146.428 59.993,-196.288 ; 62.259,-182.438 78.452,-182.438 ; 71.243,-196.288 71.243,-190.748 71.243,-185.208 ; 74.631,-184.964 74.631,-179.806 ; 82.493,-85.488 87.493,-85.488 ; 82.493,-30.088 87.493,-30.088 ; 82.493,25.294 87.493,25.294 ; 86.493,-140.888 82.493,-140.888 ; 87.493,-140.888 82.493,-140.888 ; -117.506,-199.989 -117.506,85.175 ; -117.506,-199.989 -111.472,-206.055 ; -117.506,-199.989 -117.506,-206.055 -111.472,-206.055 ; -117.506,85.175 -117.506,90.945 -111.737,90.945 ; -117.506,85.175 -111.737,90.945 ; -111.737,90.945 87.188,90.945 ; -111.472,-206.055 86.92,-206.055 ; -97.506,-196.288 -97.506,81.945 82.493,81.945 82.493,-196.288 ; -97.506,-196.288 82.493,-196.288 ; -97.507,-196.288 -97.507,-140.888 ; -97.507,-196.288 82.493,-196.288 ; -97.507,-140.888 82.493,-140.888 ; -7.506,-196.288 59.994,-196.288 ; -7.507,-196.288 59.993,-196.288 ; 59.994,-196.288 82.493,-196.288 ; 86.92,-206.055 92.493,-200.481 ; 86.92,-206.055 92.493,-206.055 92.493,-200.481 ; 87.188,90.945 92.493,90.945 92.493,85.64 ; 87.188,90.945 92.493,85.64 ; 92.493,-200.481 92.493,85.64 ; -101.506,-200.288 87.493,-200.288 87.493,85.945 -101.506,85.945 -101.506,-200.288 ; -101.506,-85.488 -97.506,-85.488 -101.506,-85.488 ; 63.347,-183.438 63.347,-181.438 69.347,-180.188 69.347,-184.688 63.347,-183.438
  text "1" at -85.452,82.489 h5
  text "2" at -44.558,82.362 h5
  text "4" at 56.915,82.362 h5
  text "3" at 6.877,82.235 h5
  text "A" at 83.204,57.216 h5
  text "A" at -100.819,55.819 h5
  text "B" at 83.458,-0.696 h5
  text "10cm-Scale with caution as distortion can occur" at -98.66,-32.827 h2.3 r90
  text "C" at 83.458,-55.687 h5
  text "D" at 83.496,-110.208 h5
  text "general tolerances (SN EN 22768-1/-2): ISO 2768-mK" at -96.771,-144.631 h3.2
  text "Indrivetec AG  confidential" at -7.068,-145.959 h6
  text "Copying of this document and giving it to others and the use or communication of the contents" at -96.749,-149.073 h2.3
  text "replacement for:" at 60.612,-149.878 h3.2
  text "checked :" at -6.941,-150.046 h3.2
  text "thereof, are forbidden without express authority. Offenders are liable to the payment of damages." at -96.749,-151.573 h2.3
  text "All rights are reserved in the event of the a patent or the registration of a utility or design." at -96.749,-154.073 h2.3
  text "checked eng:" at -7.072,-155.508 h3.2
  text "Indrivetec AG" at -96.749,-156.573 h2.3
  text "Indrivetec AG" at -46.717,-160.843 h3.4
  text "checked  prod:" at -7.051,-161.015 h3.2
  text "scale:" at 60.612,-161.059 h3.2
  text "INDRIVETEC" at -96.374,-163.764 h6.5
  text "Hagenholzstrasse 71, CH-8050 Zürich" at -60.179,-164.018 h3.4
  text "drawn by:" at -7.02,-166.422 h3.2
  text "www.indrivetec.ch" at -49.384,-166.939 h3.4
  text "1:1" at 62.693,-167.242 h4.2
  text "Innovative Drive Technologies AG" at -96.501,-167.701 h2.6
  text "E" at 83.077,-167.828 h5
  text "LK" at -2.717,-169.208 h5
  text "E" at -100.692,-169.479 h5
  text "description:" at -7.008,-170.998 h3.2
  text "material:" at 60.618,-172.161 h3.2
  text "Subject to rectifying modification and amendments" at -95.91,-172.445 h3.2
  text "d" at -95.827,-177.764 h3.2
  text "EP-17-00**-AA-I-E-A" at -1.581,-177.844 h5
  text "c" at -95.749,-183.258 h3.2
  text "article number:" at -5.981,-183.844 h3.2
  text "000-0000-00" at 9.169,-183.844 h5
  text "b" at -95.768,-188.732 h3.2
  text "format:" at 60.38,-188.835 h3.2
  text "A4" at 75.838,-189.505 h4.2
  text "CAD-name:" at -1.481,-191.094 h3.2
  text "LSB / LSB - P  V5.1" at 6.173,-193.719 h5
  text "modification:" at -91.567,-194.28 h3.2
  text "name, date:" at -26.673,-194.295 h3.2
  text "page / of:" at 60.38,-194.29 h2.9
  text "1" at 74.569,-194.961 h4.2
  text "/" at 77.505,-195 h4.2
  text "1" at 79.568,-195.003 h4.2
  text "2" at -42.399,-199.705 h5
  text "3" at 7.385,-199.705 h5
  text "1" at -84.944,-199.832 h5
  text "4" at 60.344,-199.832 h5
